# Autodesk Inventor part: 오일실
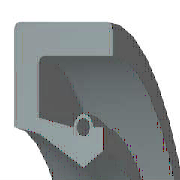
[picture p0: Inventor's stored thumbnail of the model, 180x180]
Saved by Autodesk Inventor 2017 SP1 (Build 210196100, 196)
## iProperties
IsCustomPart: 1
Created: 2015-12
Part Number: 오일실
Material: 고무
Description: 오일-실
Document SubType Name: Modeling
Standard: KS B 2804
Designer: mdu
Standards Organization: KS
Language: ko-KR
Size Designation: S - 15 30 7
Categories: <MemberInstance><Categories><Category DisplayName="샤프트 부품" InternalName="7f7aeb1f-a693-4053-b835-cee3144e0d98" Mnemonic="SHFT"><Category DisplayName="실링" Intern
Density: 0.93 g/cm^3
Appearance: 고무 - 검은색 - 버전 1.1
Mass: 1.64364 g
Surface Area: 26.6454 cm^2
Volume: 1.76736 cm^3
Author: mdu
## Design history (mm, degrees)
revolve "본체" stored, may be unused: angle "d17" = 90 deg
revolve "스프링1" stored, may be unused: angle "d18" = 90 deg
body "Solid1"
sketch "스케치1"
  geometry: L1 (0, 15)-(7, 15); L2 (7, 15)-(7, 13.75); L3 (7, 13.75)-(1.75, 13.75); L4 (0, 15)-(0, 9.6); L5 (0, 9.6)-(1.75, 9.25); L6 (1.75, 9.25)-(4.9, 7.5); L7 (4.9, 7.5)-(0, 7.5); L8 (6.3, 8.375)-(6.3, 9.6); L9 (0, 0)-(9.586, 0) reference; L10 (4.9, 7.5)-(6.3, 8.375); L11 (0, 18)-(0, -3) reference; L12 (-1.917, 0)-(11.503, 0) reference; L13 (4.2, 9.6)-(1.75, 10.09); L14 (1.75, 10.09)-(1.75, 13.75); L15 (6.3, 9.6)-(5.6, 9.6); C1 r 0.455 at (4.9, 9.6); A1 r 0.7 centre (4.9, 9.6) between (5.6, 9.6) and (4.2, 9.6)
  constraints: 26 end point, 5 horizontal alignment, 4 perpendicular, 2 centre point, 2 collinear, 2 horizontal, 2 parallel, 2 point on circle, 2 point on line, 2 vertical alignment, 1 coincident
  dimensions: "d0" = 30 diameter of L1 L9 (= SD2); "d1" = 16.75 diameter of L8.start L9 (= ABDM); "d2" = 1.25 distance of L1.end L2.end (computed from SD); "d3" = 0.91 diameter of C1 (= SPDI); "d4" = 1.4 diameter of A1 (= SPDA); "d5" = 15 diameter of L6.end L9 (= NND); "d6" = 18.5 diameter of L5.end L9 (= TKDM); "d7" = 19.2 diameter of L4.end L9 (= HLDM); "d8" = 4.9 distance from line of C1.centre L4 (= SPDST); "d9" = 6.3 distance between parallel lines of L8 L4 (= SDI); "d10" = 7 distance between parallel lines of L2 L4 (= SWDT); "d12" = 1.75 distance between parallel lines of L14 L4 (= SD)
fillet "모깎기1" dims "d11" = 0.3 (= RR)
other parameters: "SD2" = 30 [user parameter; used in 1 equation term], "SWDT" = 7 [user parameter; used in 1 equation term], "RR" = 0.3 [user parameter; used in 1 equation term], "SD" = 1.75 [user parameter; used in 2 equation terms], "NND" = 15 [user parameter; used in 1 equation term], "SPDA" = 1.4 [user parameter; used in 1 equation term], "SPDI" = 0.91 [user parameter; used in 1 equation term], "TKDM" = 18.5 [user parameter; used in 1 equation term], "HLDM" = 19.2 [user parameter; used in 1 equation term], "ABDM" = 16.75 [user parameter; used in 1 equation term], "SDI" = 6.3 [user parameter; used in 1 equation term], "SPDST" = 4.9 [user parameter; used in 1 equation term], "d13" = 0, "d14" = 0, "d15" = 0, "LAB" = 0.35 [user parameter]
